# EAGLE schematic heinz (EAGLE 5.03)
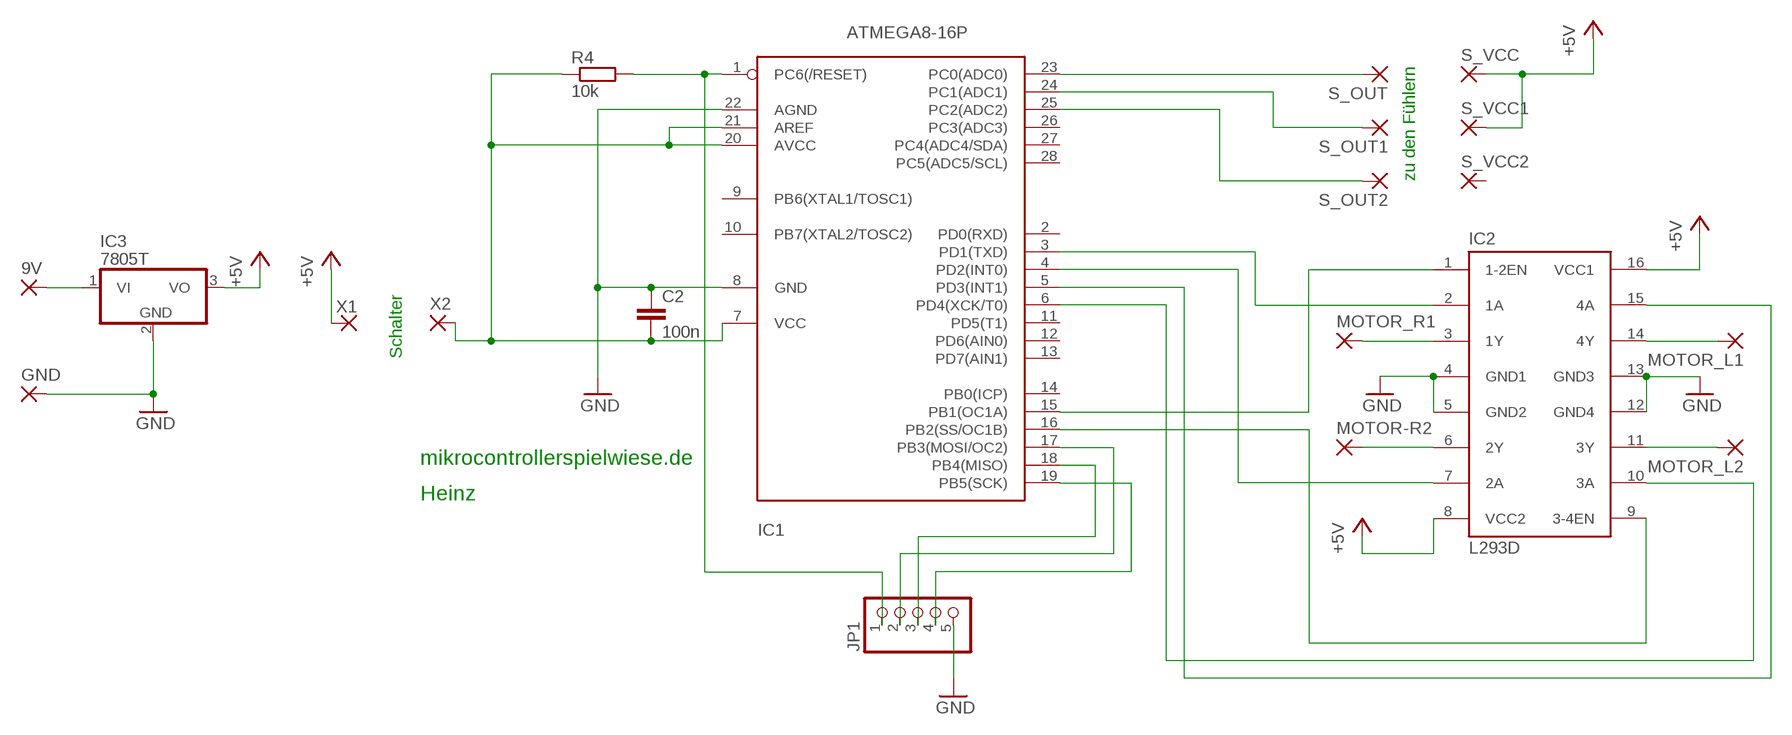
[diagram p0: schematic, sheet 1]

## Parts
9V  2,54/1,1  [2,54/1,1]
C2  100n  C-EU025-024X044  [C025-024X044]
GND  2,54/1,1  [2,54/1,1]
IC1  ATMEGA8-16P  [DIL28-3]
IC2  L293D  [DIL16]
IC3  7805T  [TO220H]
JP1  PINHD-1X5  [1X05]
MOTOR-R2  2,54/1,1  [2,54/1,1]
MOTOR_L1  2,54/1,1  [2,54/1,1]
MOTOR_L2  2,54/1,1  [2,54/1,1]
MOTOR_R1  2,54/1,1  [2,54/1,1]
R4  10k  R-EU_0207/10  [0207/10]
S_OUT  2,54/1,1  [2,54/1,1]
S_OUT1  2,54/1,1  [2,54/1,1]
S_OUT2  2,54/1,1  [2,54/1,1]
S_VCC  2,54/1,1  [2,54/1,1]
S_VCC1  2,54/1,1  [2,54/1,1]
S_VCC2  2,54/1,1  [2,54/1,1]
X1  2,54/1,1  [2,54/1,1]
X2  2,54/1,1  [2,54/1,1]

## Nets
+5V: IC2.8(VCC2) IC2.16(VCC1) IC3.3(VO) S_VCC1.1(P) S_VCC.1(P) X1.1(P)
GND: C2.1 GND.1(P) IC1.8(GND) IC1.22(AGND) IC2.4(GND1) IC2.5(GND2) IC2.12(GND4) IC2.13(GND3) IC3.2(GND) JP1.5
MOTOR_L2: IC2.11(3Y) MOTOR_L2.1(P)
N$1: IC1.3(PD1(TXD)) IC2.2(1A)
N$2: IC1.17(PB3(MOSI/OC2)) JP1.2
N$3: IC1.5(PD3(INT1)) IC2.15(4A)
N$4: IC1.16(PB2(SS/OC1B)) IC2.9(3-4EN)
N$5: IC1.15(PB1(OC1A)) IC2.1(1-2EN)
N$6: 9V.1(P) IC3.1(VI)
N$7: IC1.6(PD4(XCK/T0)) IC2.10(3A)
N$8: IC1.4(PD2(INT0)) IC2.7(2A)
N$10: IC1.23(PC0(ADC0)) S_OUT.1(P)
N$11: IC1.25(PC2(ADC2)) S_OUT2.1(P)
N$14: IC1.24(PC1(ADC1)) S_OUT1.1(P)
N$15: C2.2 IC1.7(VCC) IC1.20(AVCC) IC1.21(AREF) R4.1 X2.1(P)
N$16: IC1.18(PB4(MISO)) JP1.3
N$20: IC1.19(PB5(SCK)) JP1.4
N$23: IC2.14(4Y) MOTOR_L1.1(P)
N$24: IC1.1(PC6(/RESET)) JP1.1 R4.2
N$26: IC2.6(2Y) MOTOR-R2.1(P)
N$27: IC2.3(1Y) MOTOR_R1.1(P)
Unconnected: IC1.2(PD0(RXD)) IC1.9(PB6(XTAL1/TOSC1)) IC1.10(PB7(XTAL2/TOSC2)) IC1.11(PD5(T1)) IC1.12(PD6(AIN0)) IC1.13(PD7(AIN1)) IC1.14(PB0(ICP)) IC1.26(PC3(ADC3)) IC1.27(PC4(ADC4/SDA)) IC1.28(PC5(ADC5/SCL)) S_VCC2.1(P)

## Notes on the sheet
- zu den Fühlern
- Schalter
- mikrocontrollerspielwiese.de
- Heinz

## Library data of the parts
9V GND MOTOR-R2 MOTOR_L1 MOTOR_L2 MOTOR_R1 S_OUT S_OUT1 S_OUT2 S_VCC S_VCC1 S_VCC2 X1 X2 = wirepad:2,54/1,1: THROUGH-HOLE PAD
C2 = rcl:C-EU: CAPACITOR, European symbol
IC1 = avr:ATMEGA8*P: MICROCONTROLLER 8 Kbytes FLASH 1 kbytes SRAM 512 bytes EEPROM USART 4-channel 10 bit ADC 2-channel 8 bit ADC
IC2 = st-microelectronics:L293D: PUSH-PULL 4 CHANNEL DRIVER
IC3 = linear:78*: Positive VOLTAGE REGULATOR Source: http://cache.national.com/ds/LM/LM78L05.pdf http://www.fairchildsemi.com/ds/LM/LM7805.pdf
JP1 = pinhead:PINHD-1X5: PIN HEADER
R4 = rcl:R-EU_: RESISTOR, European symbol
